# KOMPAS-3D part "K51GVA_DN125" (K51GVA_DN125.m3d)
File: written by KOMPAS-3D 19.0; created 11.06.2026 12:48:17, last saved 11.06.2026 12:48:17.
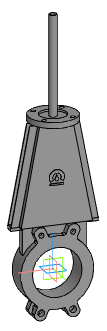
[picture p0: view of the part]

Document properties: Автор: Энергия; Полное имя файла: Z:\3.Личные\kachalov\001_3d для проектировщиков\2.6 Тип_K51GVA. Задвижка\_stp\_stp_K51GVA_DN50-DN1000_с фланцем\K51GVA_DN125.m3d

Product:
- Part/product: K51GVA_DN125

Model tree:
1. Операция без истории:1  (labels: K51GVA_DN125)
